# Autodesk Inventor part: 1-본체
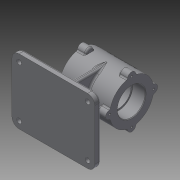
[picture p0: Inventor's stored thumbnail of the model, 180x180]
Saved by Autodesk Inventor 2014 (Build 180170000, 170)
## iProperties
Created: 2015-12
Part Number: 1-본체
Material: Generic
Document SubType Name: Modeling
Designer: test_24
Density: 1 g/cm^3
Appearance: Default
Author: test_24
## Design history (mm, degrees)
sketch "스케치1"
  geometry: L1 (-42.5, 0)-(42.5, 0); L2 (-42.5, 23.5)-(-20.5, 23.5); L3 (-20.5, 23.5)-(-20.5, 21); L4 (-20.5, 21)-(20.5, 21); L5 (20.5, 21)-(20.5, 23.5); L6 (20.5, 23.5)-(42.5, 23.5); L7 (42.5, 23.5)-(42.5, 37); L8 (42.5, 37)-(-42.5, 37); L9 (-42.5, 37)-(-42.5, 23.5); L10 (-42.5, 37)-(-42.5, 44.041); 2 further points
  constraints: 20 end point, 6 parallel, 3 collinear, 2 midpoint, 1 horizontal, 1 perpendicular, 1 point on line
  dimensions: "d0" = 85 distance between parallel lines of L7 L9; "d1" = 22 distance of L2.start L2.end; "d2" = 22 distance of L5.end L6.end; "d3" = 42 diameter of L4 L1; "d4" = 47 diameter of L6 L1; "d5" = 74 diameter of L8 L1; "d47" = 85 distance of L1.start L1.end; "d87" = 42.5 distance of point (0, 0) L1.start
revolve "회전1" sketch "스케치1" stored, may be unused: angle "d8" = 90 deg
node "작업 평면1"
sketch "스케치2"
  geometry: L1 (60, 55)-(-80, 55); L2 (-80, 55)-(-80, -55); L3 (-80, -55)-(60, -55); L4 (60, -55)-(60, 55); L5 (-42.5, 37)-(42.5, 37) reference; L6 (-42.5, -37)-(-42.5, 37) reference; 1 further point
  constraints: 8 end point, 2 parallel, 1 horizontal, 1 perpendicular
  dimensions: "d10" = 110 distance of L3.end L1.start; "d11" = 140 distance of L1.start L1.end; "d17" = 55 distance from line of point (0, 0) L1; "d18" = 37.5 distance between parallel lines of L6 L2
extrude "돌출1" join sketch "스케치2" distance "d14" = 10; taper "d15" = 0 deg
sketch "스케치6"
  geometry: L1 (-70, -55)-(-70, 55) reference; L2 (0, 37)-(-70, 37); L3 (0, -37)-(-70, -37); A1 r 37 centre (0, 0) between (0, 37) and (0, -37) reference; 1 further point
  constraints: 4 end point, 2 perpendicular, 2 point on circle, 2 point on line, 2 tangent
extrude "돌출3" join sketch "스케치6" stored distance "d22" = 8; taper "d23" = 0 deg
sketch "스케치7"
  geometry: L1 (-42.5, -37)-(42.5, -37) reference; L2 (60, -70)-(-80, -70) reference; L3 (-25, -70)-(-20.948, -37); L4 (20.948, -37)-(25, -70); 1 further point
  constraints: 4 end point, 4 point on line
  dimensions: "d24" = 97 deg angle of L2 L4; "d25" = 97 deg angle of L2 L3; "d62" = 25 horizontal distance of point (0, 0) L3.start; "d63" = 25 horizontal distance of L4.end point (0, 0)
feature "리브1" dims "d29" = 1, "d30" = 12, "d31" = 0, "d32" = 0, "d33" = 1, "d34" = 1
feature "리브2" dims "d35" = 1, "d36" = 12, "d37" = 0, "d38" = 0, "d39" = 1, "d40" = 1
sketch "스케치9"
  geometry: L1 (0, 37)-(0, -37); L2 (-37, 0)-(37, 0); A1 r 7 centre (0, 37) between (6.969, 36.338) and (-6.969, 36.338); A2 r 7 centre (37, 0) between (36.338, -6.969) and (36.338, 6.969); A3 r 7 centre (-37, 0) between (-36.338, 6.969) and (-36.338, -6.969); A4 r 7 centre (0, -37) between (-6.969, -36.338) and (6.969, -36.338); 3 further points
  constraints: 8 point on circle, 4 centre point, 4 end point, 4 midpoint, 3 coincident, 1 equal radius, 1 horizontal alignment, 1 perpendicular, 1 vertical, 13 other
  dimensions: "d42" = 14 diameter of A1; "d43" = 14 diameter of A3; "d44" = 14 diameter of A4
extrude "돌출4" join sketch "스케치9" distance "d45" = 15; taper "d46" = 0 deg
fillet "모깎기1" dims "d49" = 12
sketch "스케치10"
  geometry: L1 (48, 55)-(-68, 55) reference; L2 (-80, 43)-(-80, -43) reference; C1 r 4 at (-68, 43); 1 further point
  constraints: 1 centre point
  dimensions: "d51" = 12 distance from line of L1 C1.centre; "d52" = 12 distance from line of C1.centre L2; "d53" = 8 diameter of C1
extrude "돌출5" cut sketch "스케치10" distance "d54" = 15; taper "d55" = 0 deg
sketch "스케치11"
  geometry: A1 r 7 centre (0, 0) between (0.662, 6.969) and (0.662, -6.969) reference; A2 r 7 centre (37, -37) between (30.031, -36.338) and (43.969, -36.338) reference; A3 r 7 centre (74, 0) between (73.338, -6.969) and (73.338, 6.969) reference; A4 r 7 centre (37, 37) between (43.969, 36.338) and (30.031, 36.338) reference; 4 further points
  constraints: 4 coincident
hole "구멍1" sketch "스케치11" at (37, 37), (74, 0), (37, -37), (0, 0) diameter "d64" = 3.242; stored, may be unused: countersink angle "d68" = 90 deg, drill point angle "d70" = 118 deg; dims "d65" = 9, "d66" = 4, "d67" = 2, "d69" = 11
chamfer "모따기1" distance "d71" = 1; stored, may be unused: second distance "d72" = 2, angle "d73" = 45 deg
fillet "모깎기2" dims "d74" = 0.3
fillet "모깎기3" dims "d75" = 3
fillet "모깎기4" dims "d76" = 3
fillet "모깎기5" dims "d77" = 3
fillet "모깎기6" dims "d78" = 3
fillet "모깎기7" dims "d79" = 3
fillet "모깎기8" dims "d80" = 3
node "작업 평면5"
sketch "스케치12"
  geometry: L1 (0, -67)-(0, 0) reference; L2 (0, 0)-(37, 0); L3 (37, 0)-(10.837, 26.163); A1 r 37 centre (37, 0) between (27.896, 35.863) and (1.138, 9.104) reference; A2 r 37 centre (37, 0) between (72.862, 9.104) and (46.104, 35.862) reference; A3 r 37 centre (37, 0) between (41.188, 36.762) and (32.812, 36.762) reference; 1 further point
  constraints: 4 end point, 1 perpendicular, 1 point on circle
  dimensions: "d82" = 45 deg angle of L2 L3
node "작업 평면6"
sketch "스케치13"
  geometry: 2 further points
  constraints: 1 other
feature "엠보싱1" sketch "스케치13" dims "d83" = 0.5, "d84" = 0
fillet "모깎기9" dims "d85" = 3
fillet "모깎기10" dims "d86" = 3
node "솔리드1"
pattern_linear "직사각형 패턴1" dims "d58" = 116
pattern_linear "직사각형 패턴2" dims "d61" = 86
mirror "대칭1"
mirror "대칭2"
